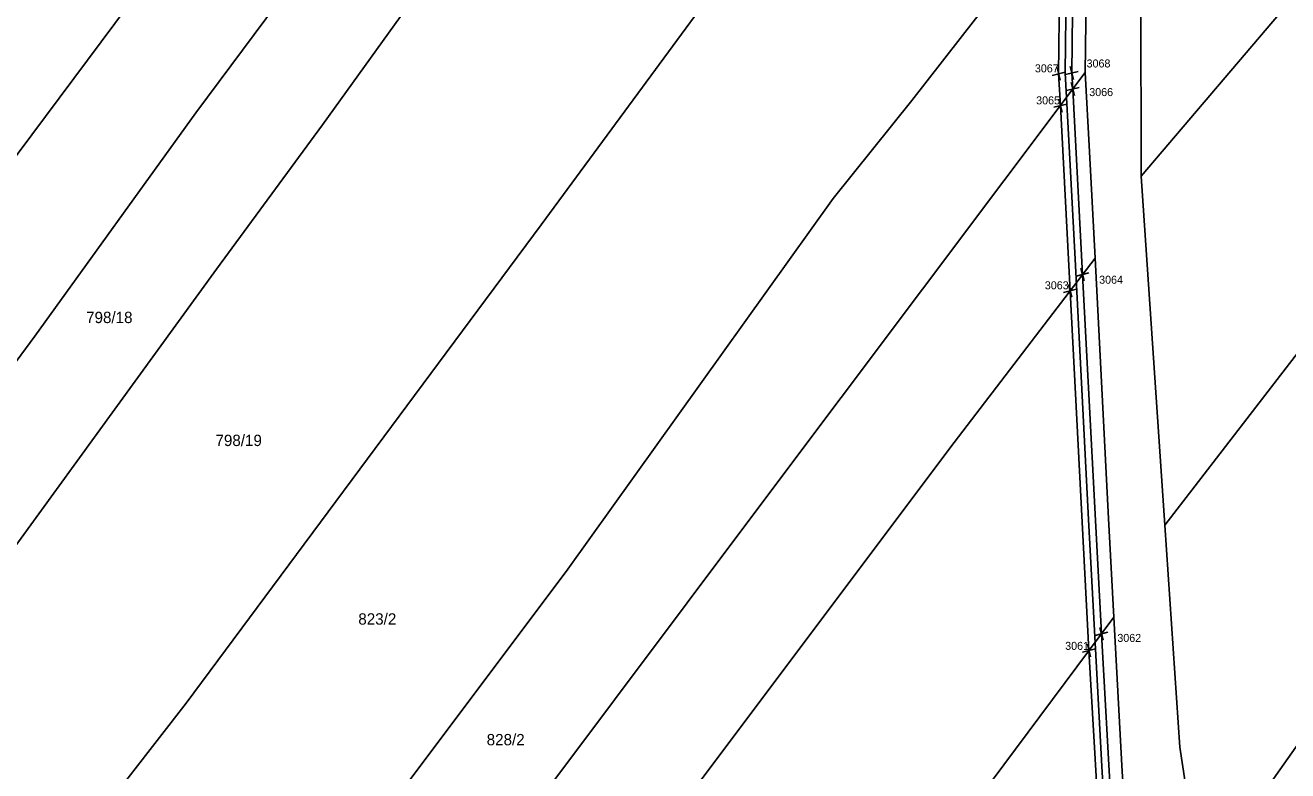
# Model space of a CAD drawing. Extents: x -7476540 to -746055, y -11317203 to -1129777.
# Drawn here: x -747735.8 to -747546.5, y -1131530.2 to -1131418.4 of the extents above; entities that cross this region are included whole.
import ezdxf

# ---------------------------------------------------------------- set-up
doc = ezdxf.new("R2010")
doc.units = 0
for name, color, linetype in [('_TRASA_vedení kabelu_CEZ', 7, 'Continuous'), ('Hranice parcel', 7, 'Continuous'), ('obvod_stavby_DZ_DO_ZPF', 7, 'Continuous'), ('Parcelní čísla', 7, 'Continuous'), ('Vrstva 60', 7, 'Continuous')]:
    doc.layers.add(name, color=color, linetype=linetype)

# ---------------------------------------------------------------- blocks, each defined once
blk = doc.blocks.new('POINT_DISPLAY')
for p, q in [((-0.7, -0.7), (0.7, 0.7)), ((-0.7, 0.7), (0.7, -0.7))]:
    blk.add_line(p, q)

msp = doc.modelspace()

# ---------------------------------------------------------------- linework, layer by layer
at = {"layer": '_TRASA_vedení kabelu_CEZ'}
msp.add_lwpolyline([(-747606.66, -1131708.94), (-747603.52, -1131695.37), (-747628.04, -1131689.7), (-747599.97, -1131653.35), (-747599.82, -1131650.35), (-747590.15, -1131609.62), (-747577.85, -1131574.83), (-747576.11, -1131566), (-747573.02, -1131550.26), (-747574.14, -1131533.4), (-747574.33, -1131530.46), (-747575.58, -1131507.34), (-747576.38, -1131492.52), (-747578.4, -1131453.5), (-747579.22, -1131437.56), (-747579.88, -1131425.59), (-747579.54, -1131395.96)], dxfattribs=at)
at = {"layer": 'Hranice parcel'}
for p, q in [((-747576.54, -1131395.88), (-747576.88, -1131425.52)), ((-747537.66, -1131404.8), (-747568.52, -1131441.05)), ((-747568.52, -1131441.05), (-747568.57, -1131412.15)), ((-747564.97, -1131493.37), (-747515.93, -1131429.75)), ((-747564.97, -1131493.37), (-747568.52, -1131441.05))]:
    msp.add_line(p, q, dxfattribs=at)
for points in [[(-747879, -1131625.66), (-747851.66, -1131591.69), (-747829.65, -1131563.42), (-747808.64, -1131535.34), (-747757.65, -1131465.52), (-747713.97, -1131406.96), (-747691.09, -1131375.78), (-747664.28, -1131339.63), (-747646.2, -1131316.75), (-747642.09, -1131312.59)], [(-747860.06, -1131629.88), (-747832.75, -1131596.26), (-747816.97, -1131575.83), (-747776.82, -1131523.47), (-747762.78, -1131503.59), (-747734.31, -1131465.05), (-747710.2, -1131431.58), (-747690.98, -1131405.7), (-747669.96, -1131376.28), (-747627.04, -1131321.32)], [(-747842.01, -1131634.16), (-747811.79, -1131593.14), (-747801.87, -1131584.09), (-747752.07, -1131516.87), (-747707.12, -1131455.02), (-747691.23, -1131433.37), (-747676.82, -1131413.33), (-747658, -1131388.25), (-747620.26, -1131339), (-747608.88, -1131328.87)], [(-747806.67, -1131645.86), (-747760.08, -1131583.56), (-747741.05, -1131557.9), (-747711.67, -1131520.04), (-747658.45, -1131448.35), (-747613.7, -1131387.55), (-747586.28, -1131353.77)], [(-747772.35, -1131654.05), (-747742.69, -1131616.2), (-747708.15, -1131571.7), (-747696.05, -1131555.49), (-747654.43, -1131499.96), (-747614.66, -1131444.39), (-747602.9, -1131429.72), (-747576.54, -1131395.88)], [(-747751.97, -1131658.69), (-747725.51, -1131622.95), (-747709.1, -1131600.51), (-747691.54, -1131577.63), (-747669.23, -1131548.64), (-747625.65, -1131490.48), (-747576.88, -1131425.52)], [(-747576.88, -1131425.52), (-747576.22, -1131437.4), (-747575.4, -1131453.35)], [(-747575.4, -1131453.35), (-747596.53, -1131480.99), (-747637.49, -1131535.62), (-747681.61, -1131594.97), (-747707.2, -1131626.86), (-747733.77, -1131662.83)], [(-747575.4, -1131453.35), (-747573.38, -1131492.36), (-747572.58, -1131507.18)], [(-747559.72, -1131546.32), (-747549.84, -1131533.09), (-747519.12, -1131489.53), (-747492.83, -1131454.72)], [(-747559.72, -1131546.32), (-747562.72, -1131526.64), (-747564.97, -1131493.37)], [(-747698.69, -1131671.28), (-747664.74, -1131625.11), (-747629.09, -1131580.38), (-747591, -1131531.84), (-747572.58, -1131507.18)], [(-747572.58, -1131507.18), (-747571.34, -1131530.28), (-747571.15, -1131533.2)]]:
    msp.add_lwpolyline(points, dxfattribs=at)
at = {"layer": 'obvod_stavby_DZ_DO_ZPF'}
for points in [[(-747626.3, -1131689.08), (-747598.98, -1131653.55), (-747598.83, -1131650.49), (-747589.19, -1131609.9), (-747576.88, -1131575.09), (-747575.89, -1131570.02), (-747572.01, -1131550.32), (-747573, -1131535.54), (-747574.45, -1131509.68), (-747577.28, -1131455.8), (-747578.74, -1131428), (-747578.88, -1131425.6), (-747578.57, -1131398.49)], [(-747580.6, -1131401.09), (-747580.88, -1131425.73), (-747580.61, -1131430.49), (-747579.15, -1131458.31), (-747576.32, -1131512.18), (-747574.85, -1131537.87), (-747574.03, -1131550.19), (-747578.6, -1131573.46), (-747578.82, -1131574.56), (-747591.11, -1131609.34), (-747600.82, -1131650.21), (-747600.95, -1131652.99), (-747628.4, -1131688.54)]]:
    msp.add_lwpolyline(points, dxfattribs=at)
at = {"layer": 'Vrstva 60'}
for p, q in [((-747580.88, -1131425.73), (-747580.88, -1131425.73)), ((-747578.88, -1131425.6), (-747578.88, -1131425.6)), ((-747578.74, -1131428), (-747578.74, -1131428)), ((-747580.61, -1131430.49), (-747580.61, -1131430.49)), ((-747577.28, -1131455.8), (-747577.28, -1131455.8)), ((-747579.15, -1131458.31), (-747579.15, -1131458.31)), ((-747574.45, -1131509.68), (-747574.45, -1131509.68)), ((-747576.32, -1131512.18), (-747576.32, -1131512.18))]:
    msp.add_line(p, q, dxfattribs=at)

# ---------------------------------------------------------------- block references
at = {"layer": 'obvod_stavby_DZ_DO_ZPF', "rotation": 149.23018890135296}
for p in [(-747580.87, -1131425.73), (-747578.88, -1131425.6), (-747578.74, -1131428), (-747580.61, -1131430.49), (-747577.28, -1131455.8), (-747579.16, -1131458.26), (-747574.45, -1131509.68), (-747576.32, -1131512.18)]:
    msp.add_blockref('POINT_DISPLAY', p, dxfattribs=at)

# ---------------------------------------------------------------- texts
at = {"layer": 'Parcelní čísla'}
for s, p in [('798/18', (-747726.64, -1131463.09)), ('798/19', (-747707.25, -1131481.52)), ('823/2', (-747685.84, -1131508.29)), ('828/2', (-747666.6, -1131526.38))]:
    msp.add_text(s, height=1.7, dxfattribs=at).set_placement(p)
at = {"layer": 'Vrstva 60'}
for s, p in [('3068', (-747576.68, -1131424.77)), ('3067', (-747584.43, -1131425.5)), ('3065', (-747584.24, -1131430.3)), ('3066', (-747576.28, -1131429.06)), ('3063', (-747582.94, -1131458.02)), ('3064', (-747574.8, -1131457.19)), ('3062', (-747572.07, -1131510.88)), ('3061', (-747579.89, -1131512.07))]:
    msp.add_text(s, height=1.2, dxfattribs=at).set_placement(p)

doc.saveas('drawing.dxf')
